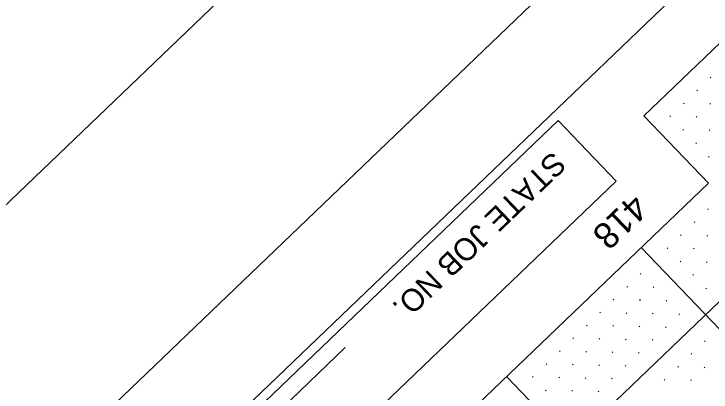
# Model space of a CAD drawing. Extents: x 2148987 to 2151117, y 142806 to 144993.
# Drawn here: x 2149110.7 to 2149297.8, y 143738.1 to 143839.6 of the extents above; entities that cross this region are included whole.
import ezdxf

# ---------------------------------------------------------------- set-up
doc = ezdxf.new("R2010")
doc.units = 0
for name, color, linetype in [('BASELINE', 7, 'Continuous'), ('PR_ABUT_PH3', 7, 'Continuous'), ('PR_PIER_PH3', 7, 'Continuous'), ('PR_PIER_PH4', 7, 'Continuous'), ('PR_Road_Concrete', 7, 'Continuous'), ('PR_Slopewall_Ph4', 7, 'Continuous'), ('SHT_Profile_Grid_Minor', 7, 'Continuous'), ('Wall D Bore Txt', 7, 'Continuous')]:
    doc.layers.add(name, color=color, linetype=linetype)

msp = doc.modelspace()

# ---------------------------------------------------------------- linework, layer by layer
at = {"layer": 'BASELINE'}
msp.add_lwpolyline([(2151029.45, 144024.32), (2149802.07, 142848.08), (2149040.98, 143642.27), (2150268.36, 144818.51)], close=True, dxfattribs=at)
at = {"layer": 'PR_ABUT_PH3'}
msp.add_lwpolyline([(2151117.11, 144051.19), (2149817.52, 142805.76), (2148987.24, 143672.15), (2150286.82, 144917.58)], close=True, dxfattribs=at)
at = {"layer": 'PR_PIER_PH3'}
for p, q in [((2150261.97, 144684.26), (2149124.83, 143594.52)), ((2149279.01, 143776.89), (2149576.53, 143466.44)), ((2149242.91, 143742.3), (2149540.43, 143431.84))]:
    msp.add_line(p, q, dxfattribs=at)
at = {"layer": 'PR_PIER_PH4'}
msp.add_line((2149199.59, 143750.04), (2149147.09, 143699.73), dxfattribs=at)
at = {"layer": 'PR_Road_Concrete'}
msp.add_line((2150227.37, 144720.36), (2149279.76, 143812.24), dxfattribs=at)
for points in [[(2150941.76, 143974.91), (2149804.63, 142885.16), (2149078.13, 143643.25), (2150215.26, 144733)], [(2149272.31, 143794.72), (2149256.75, 143810.96), (2149081.66, 143643.18), (2149097.23, 143626.93)]]:
    msp.add_lwpolyline(points, close=True, dxfattribs=at)
msp.add_lwpolyline([(2149279.76, 143812.24), (2149297.06, 143794.19), (2149134.61, 143638.51)], dxfattribs=at)
at = {"layer": 'SHT_Profile_Grid_Minor'}
for p, q in [((2149297.75, 143822.56), (2149297.57, 143822.38)), ((2149294.14, 143819.1), (2149293.96, 143818.92)), ((2149290.53, 143815.64), (2149290.35, 143815.46)), ((2149297.6, 143815.49), (2149297.42, 143815.31)), ((2149286.92, 143812.18), (2149286.74, 143812)), ((2149293.99, 143812.03), (2149293.81, 143811.85)), ((2149290.38, 143808.57), (2149290.2, 143808.39)), ((2149297.45, 143808.42), (2149297.27, 143808.24)), ((2149293.84, 143804.96), (2149293.66, 143804.78)), ((2149297.3, 143801.35), (2149297.12, 143801.17)), ((2149297, 143787.21), (2149296.82, 143787.04)), ((2149293.39, 143783.75), (2149293.21, 143783.58)), ((2149289.78, 143780.29), (2149289.6, 143780.12)), ((2149296.85, 143780.14), (2149296.67, 143779.97)), ((2149286.17, 143776.83), (2149285.99, 143776.66)), ((2149293.24, 143776.68), (2149293.06, 143776.51)), ((2149289.63, 143773.22), (2149289.45, 143773.05)), ((2149296.7, 143773.07), (2149296.52, 143772.9)), ((2149278.95, 143769.91), (2149278.77, 143769.74)), ((2149293.09, 143769.61), (2149292.91, 143769.44)), ((2149275.34, 143766.45), (2149275.16, 143766.28)), ((2149282.41, 143766.3), (2149282.23, 143766.13)), ((2149296.55, 143766), (2149296.37, 143765.83)), ((2149271.73, 143762.99), (2149271.55, 143762.82)), ((2149278.8, 143762.84), (2149278.62, 143762.67)), ((2149285.87, 143762.69), (2149285.69, 143762.52)), ((2149268.12, 143759.53), (2149267.94, 143759.36)), ((2149275.19, 143759.38), (2149275.01, 143759.21)), ((2149282.26, 143759.23), (2149282.08, 143759.06)), ((2149289.33, 143759.08), (2149289.15, 143758.91)), ((2149264.51, 143756.07), (2149264.33, 143755.9)), ((2149271.58, 143755.92), (2149271.4, 143755.75)), ((2149278.65, 143755.77), (2149278.47, 143755.6)), ((2149285.72, 143755.62), (2149285.54, 143755.45)), ((2149260.9, 143752.61), (2149260.72, 143752.44)), ((2149267.97, 143752.46), (2149267.79, 143752.29)), ((2149275.04, 143752.31), (2149274.86, 143752.14)), ((2149282.11, 143752.16), (2149281.93, 143751.99)), ((2149296.24, 143751.86), (2149296.06, 143751.69)), ((2149257.29, 143749.15), (2149257.11, 143748.98)), ((2149264.36, 143749), (2149264.18, 143748.83)), ((2149271.43, 143748.85), (2149271.25, 143748.68)), ((2149278.5, 143748.7), (2149278.32, 143748.53)), ((2149292.63, 143748.4), (2149292.45, 143748.23)), ((2149253.68, 143745.69), (2149253.5, 143745.52)), ((2149260.75, 143745.54), (2149260.57, 143745.37)), ((2149267.82, 143745.39), (2149267.64, 143745.22)), ((2149274.89, 143745.24), (2149274.71, 143745.07)), ((2149289.02, 143744.94), (2149288.84, 143744.77)), ((2149296.09, 143744.79), (2149295.91, 143744.62)), ((2149250.07, 143742.23), (2149249.89, 143742.06)), ((2149257.14, 143742.08), (2149256.96, 143741.91)), ((2149264.21, 143741.93), (2149264.03, 143741.76)), ((2149271.28, 143741.78), (2149271.1, 143741.61)), ((2149285.41, 143741.48), (2149285.23, 143741.31)), ((2149292.48, 143741.33), (2149292.3, 143741.16)), ((2149253.53, 143738.62), (2149253.35, 143738.45)), ((2149260.6, 143738.47), (2149260.42, 143738.3)), ((2149267.67, 143738.32), (2149267.49, 143738.15))]:
    msp.add_line(p, q, dxfattribs=at)

# ---------------------------------------------------------------- texts
at = {"layer": 'PR_Slopewall_Ph4'}
msp.add_text('STATE JOB NO.', height=6, rotation=223.7809, dxfattribs=at).set_placement((2149255.26, 143802.97))
at = {"layer": 'Wall D Bore Txt'}
msp.add_text('418', height=7, rotation=223.7809, dxfattribs=at).set_placement((2149276.73, 143791.67))

doc.saveas('drawing.dxf')
